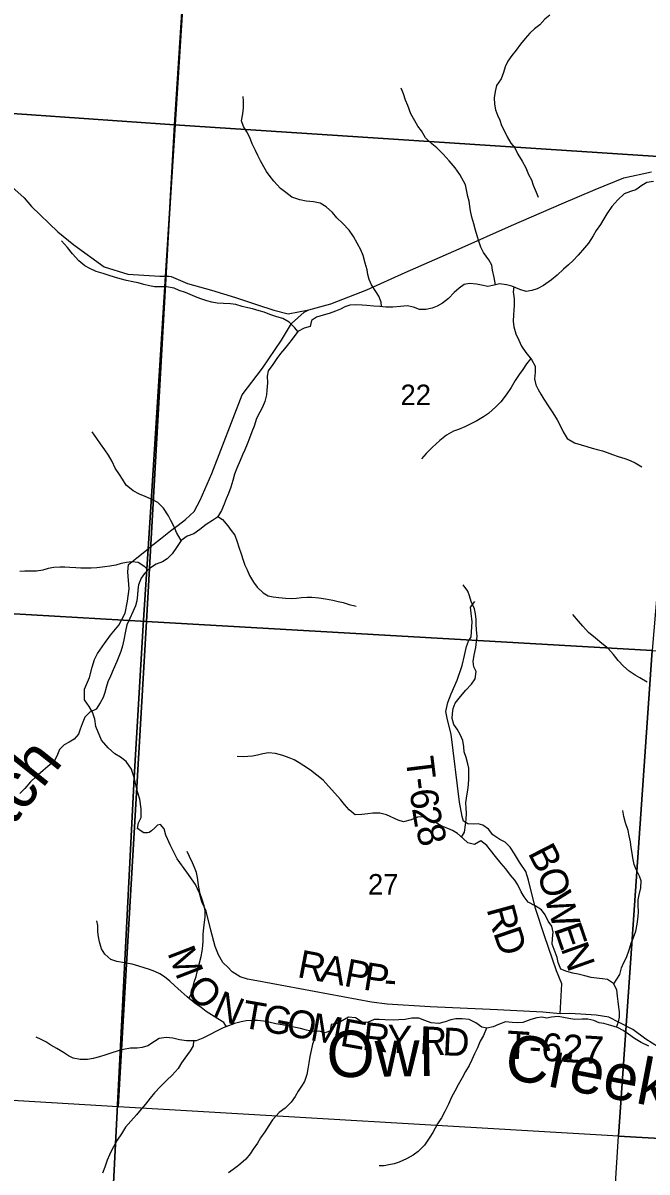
# Model space of a CAD drawing. Extents: x 1578669 to 1989827, y 208020 to 553079.
# Drawn here: x 1838245 to 1844968, y 352759 to 365146 of the extents above; entities that cross this region are included whole.
import ezdxf

# ---------------------------------------------------------------- set-up
doc = ezdxf.new("R2010")
doc.units = 0
for name, color, linetype in [('GM_X_County_Road', 7, 'Continuous'), ('GM_X_Minor_River', 7, 'Continuous'), ('GM_X_Minor_River_Text', 7, 'Continuous'), ('GM_X_Section', 7, 'Continuous'), ('GM_X_Section_Text', 7, 'Continuous'), ('GM_X_Township', 7, 'Continuous'), ('GM_X_Township_Road', 7, 'Continuous'), ('GM_X_Township_Road_Text', 7, 'Continuous')]:
    doc.layers.add(name, color=color, linetype=linetype)

msp = doc.modelspace()

# ---------------------------------------------------------------- linework, layer by layer
at = {"layer": 'GM_X_County_Road'}
for points in [[(1836042, 365335), (1836459, 365085), (1836745, 364850), (1836898, 364717), (1837003, 364579), (1837136, 364380), (1837234, 364169), (1837353, 363879), (1837487, 363752), (1837696, 363686), (1837824, 363590), (1838061, 363436), (1838256, 363262), (1838336, 363168), (1838621, 362894), (1838792, 362754), (1839121, 362517), (1839376, 362437), (1839718, 362416), (1839780, 362416), (1839788, 362417)], [(1839788, 362417), (1839790, 362417), (1839816, 362418), (1839842, 362413), (1840018, 362339), (1840276, 362265), (1840534, 362187), (1840759, 362110), (1840947, 362051), (1841103, 362011), (1841324, 362054), (1841561, 362118), (1841951, 362269), (1842363, 362458), (1842944, 362711), (1843509, 362963), (1844048, 363197), (1844408, 363351), (1844720, 363476), (1845017, 363542)]]:
    msp.add_lwpolyline(points, dxfattribs=at)
at = {"layer": 'GM_X_Minor_River'}
for points in [[(1843921, 365230), (1843868, 365187), (1843814, 365128), (1843755, 365082), (1843704, 365035), (1843656, 364980), (1843605, 364918), (1843557, 364853), (1843511, 364794), (1843468, 364733), (1843440, 364673), (1843423, 364614), (1843397, 364544), (1843348, 364472)], [(1843336, 362324), (1843320, 362404), (1843305, 362481), (1843296, 362535), (1843265, 362594), (1843205, 362671), (1843176, 362730), (1843157, 362794), (1843138, 362853), (1843119, 362913), (1843101, 362982), (1843082, 363052), (1843067, 363122), (1843060, 363173), (1843051, 363227), (1843038, 363277), (1843027, 363328), (1843011, 363402), (1842953, 363512), (1842902, 363585), (1842838, 363660), (1842773, 363731), (1842702, 363801), (1842651, 363844), (1842582, 363908), (1842537, 363983), (1842500, 364035), (1842465, 364090), (1842423, 364167), (1842391, 364256), (1842366, 364315), (1842343, 364381), (1842320, 364444)], [(1843348, 364472), (1843334, 364408), (1843323, 364340), (1843326, 364270), (1843337, 364209), (1843357, 364151), (1843382, 364098), (1843401, 364042), (1843428, 363987), (1843463, 363918), (1843500, 363850), (1843545, 363799), (1843576, 363732), (1843624, 363655), (1843661, 363584), (1843693, 363511), (1843722, 363454), (1843743, 363398), (1843774, 363323), (1843795, 363269)], [(1842107, 362090), (1842105, 362135), (1842077, 362200), (1842048, 362253), (1842001, 362324), (1841976, 362380), (1841961, 362433), (1841952, 362485), (1841933, 362557), (1841911, 362638), (1841886, 362699), (1841844, 362774), (1841805, 362845), (1841758, 362912), (1841688, 362989), (1841625, 363047), (1841578, 363104), (1841513, 363163), (1841445, 363204), (1841374, 363218), (1841296, 363227), (1841226, 363241), (1841142, 363268), (1841075, 363318), (1841018, 363361), (1840948, 363441), (1840909, 363493), (1840869, 363544), (1840838, 363597), (1840804, 363660), (1840775, 363717), (1840750, 363773), (1840713, 363844), (1840688, 363911), (1840658, 363971), (1840619, 364032), (1840598, 364093), (1840613, 364167), (1840622, 364231), (1840622, 364303), (1840617, 364353)], [(1845039, 363439), (1844967, 363426), (1844914, 363395), (1844849, 363346), (1844791, 363329), (1844722, 363303), (1844653, 363238), (1844590, 363167), (1844534, 363088), (1844503, 363036), (1844468, 362975), (1844420, 362908), (1844387, 362850), (1844338, 362773), (1844293, 362722), (1844225, 362643), (1844172, 362584), (1844121, 362539), (1844068, 362492), (1844001, 362429), (1843940, 362376), (1843853, 362316), (1843784, 362281), (1843727, 362264), (1843665, 362251), (1843599, 362272), (1843512, 362310), (1843456, 362325), (1843380, 362335), (1843320, 362320), (1843254, 362307), (1843184, 362319), (1843130, 362330), (1843056, 362339), (1842998, 362326), (1842945, 362289), (1842890, 362240), (1842829, 362175), (1842764, 362124), (1842707, 362095), (1842655, 362072), (1842584, 362058), (1842518, 362059), (1842453, 362082), (1842385, 362096), (1842311, 362091), (1842229, 362081), (1842155, 362084), (1842091, 362091), (1842025, 362095), (1841951, 362100)], [(1841207, 361822), (1841175, 361859), (1841112, 361920), (1841043, 361960), (1840979, 361977), (1840906, 362004), (1840844, 362028), (1840788, 362043), (1840719, 362064), (1840667, 362077), (1840607, 362090), (1840538, 362110), (1840480, 362119), (1840404, 362123), (1840338, 362126), (1840278, 362135), (1840226, 362152), (1840172, 362169), (1840121, 362188), (1840047, 362218), (1839996, 362239), (1839928, 362264), (1839874, 362287), (1839791, 362301), (1839722, 362300), (1839662, 362301), (1839607, 362311), (1839545, 362326), (1839485, 362345), (1839429, 362354), (1839359, 362370), (1839290, 362387), (1839232, 362406), (1839174, 362423), (1839107, 362445), (1839033, 362468), (1838964, 362500), (1838912, 362529), (1838847, 362582), (1838778, 362656), (1838726, 362725), (1838659, 362796)], [(1843532, 362301), (1843525, 362248), (1843538, 362173), (1843538, 362103), (1843533, 362049), (1843530, 361999), (1843527, 361933), (1843532, 361869), (1843554, 361796), (1843587, 361727), (1843616, 361661), (1843662, 361594), (1843725, 361518), (1843762, 361446), (1843764, 361381), (1843757, 361309), (1843770, 361245), (1843797, 361194), (1843826, 361144), (1843855, 361091), (1843902, 361018), (1843954, 360943), (1844001, 360868), (1844037, 360799), (1844066, 360738), (1844107, 360665), (1844186, 360620), (1844260, 360598), (1844320, 360581), (1844377, 360564), (1844433, 360549), (1844489, 360533), (1844540, 360516), (1844598, 360493), (1844658, 360474), (1844729, 360451), (1844785, 360431), (1844839, 360406), (1844912, 360361)], [(1841951, 362100), (1841899, 362105), (1841829, 362109), (1841765, 362104), (1841714, 362087), (1841664, 362062), (1841611, 362041), (1841543, 362016), (1841480, 361997), (1841408, 361975), (1841353, 361940), (1841340, 361874), (1841273, 361857), (1841207, 361822), (1841145, 361739), (1841104, 361688), (1841061, 361635), (1841020, 361583), (1840981, 361530), (1840935, 361463), (1840888, 361398), (1840877, 361340), (1840878, 361267), (1840872, 361189), (1840869, 361139), (1840852, 361064), (1840826, 361004), (1840795, 360952), (1840762, 360883), (1840734, 360799), (1840711, 360738), (1840686, 360670), (1840659, 360604), (1840635, 360545), (1840610, 360491), (1840585, 360430), (1840550, 360348), (1840524, 360284), (1840507, 360213), (1840484, 360143), (1840458, 360073), (1840435, 360016), (1840414, 359960), (1840385, 359890), (1840339, 359817), (1840286, 359782), (1840220, 359741), (1840150, 359685), (1840085, 359640), (1840015, 359615), (1839948, 359566), (1839900, 359491), (1839853, 359424), (1839798, 359371), (1839747, 359338), (1839679, 359311), (1839608, 359264), (1839555, 359211), (1839518, 359160), (1839490, 359088), (1839481, 359036), (1839480, 358982), (1839471, 358918), (1839456, 358862), (1839429, 358799), (1839395, 358725), (1839364, 358658), (1839349, 358590), (1839331, 358498), (1839317, 358430), (1839298, 358369), (1839277, 358317), (1839254, 358261), (1839218, 358174), (1839187, 358106), (1839160, 358043), (1839141, 357981), (1839126, 357929), (1839107, 357873), (1839077, 357816), (1839032, 357749), (1838965, 357716), (1838910, 357663), (1838883, 357591), (1838860, 357533), (1838841, 357478), (1838796, 357426), (1838741, 357394), (1838688, 357366), (1838639, 357313), (1838610, 357242), (1838581, 357188), (1838514, 357129), (1838463, 357088), (1838383, 357018), (1838324, 356965), (1838265, 356892), (1838212, 356841)], [(1843716, 361530), (1843670, 361471), (1843631, 361412), (1843590, 361355), (1843547, 361291), (1843503, 361216), (1843451, 361137), (1843392, 361062), (1843343, 361011), (1843261, 360936), (1843207, 360899), (1843134, 360857), (1843055, 360816), (1843004, 360793), (1842938, 360764), (1842885, 360747), (1842807, 360703), (1842737, 360644), (1842656, 360575), (1842590, 360504), (1842537, 360449)], [(1839950, 359568), (1839900, 359655), (1839877, 359706), (1839838, 359783), (1839811, 359833), (1839758, 359915), (1839696, 359976), (1839618, 360016), (1839561, 360043), (1839501, 360068), (1839432, 360101), (1839357, 360163), (1839316, 360228), (1839285, 360279), (1839238, 360348), (1839206, 360417), (1839165, 360488), (1839128, 360546), (1839079, 360611), (1839042, 360666), (1838990, 360737)], [(1840344, 359825), (1840393, 359792), (1840452, 359727), (1840489, 359676), (1840528, 359623), (1840554, 359552), (1840571, 359494), (1840594, 359425), (1840617, 359355), (1840636, 359302), (1840661, 359250), (1840685, 359189), (1840730, 359118), (1840769, 359065), (1840834, 359002), (1840887, 358969), (1840939, 358960), (1841003, 358954), (1841073, 358945), (1841137, 358942), (1841193, 358945), (1841247, 358954), (1841306, 358958), (1841358, 358957), (1841433, 358950), (1841505, 358940), (1841583, 358923), (1841639, 358910), (1841693, 358897), (1841760, 358877), (1841836, 358858)], [(1839591, 359248), (1839558, 359283), (1839485, 359329), (1839419, 359336), (1839361, 359331), (1839301, 359318), (1839244, 359302), (1839180, 359289), (1839128, 359282), (1839039, 359271), (1838981, 359269), (1838931, 359270), (1838867, 359269), (1838815, 359272), (1838749, 359275), (1838697, 359278), (1838643, 359279), (1838577, 359275), (1838515, 359264), (1838460, 359249), (1838390, 359238), (1838336, 359237), (1838264, 359237), (1838212, 359232)], [(1842971, 356368), (1843002, 356422), (1843014, 356502), (1843021, 356560), (1843024, 356628), (1843019, 356682), (1843016, 356740), (1843026, 356814), (1843039, 356876), (1843046, 356936), (1843049, 356996), (1843050, 357054), (1843047, 357111), (1843038, 357161), (1843018, 357229), (1842999, 357290), (1842994, 357342), (1842983, 357410), (1842956, 357475), (1842924, 357534), (1842888, 357585), (1842868, 357649), (1842871, 357703), (1842878, 357755), (1842903, 357815), (1842960, 357886), (1843016, 357953), (1843077, 358018), (1843116, 358075), (1843126, 358155), (1843103, 358206), (1843096, 358262), (1843107, 358332), (1843123, 358414), (1843132, 358478), (1843137, 358534), (1843132, 358606), (1843127, 358662), (1843127, 358716), (1843122, 358775), (1843109, 358831), (1843072, 358908), (1843057, 358970), (1843036, 359021), (1842986, 359088)], [(1844969, 358039), (1844892, 358087), (1844840, 358114), (1844777, 358157), (1844714, 358212), (1844659, 358272), (1844607, 358339), (1844550, 358402), (1844483, 358457), (1844412, 358515), (1844339, 358576), (1844278, 358642), (1844231, 358699), (1844170, 358770)], [(1844641, 354320), (1844660, 354378), (1844671, 354429), (1844672, 354486), (1844665, 354538), (1844659, 354598), (1844652, 354656), (1844643, 354723), (1844608, 354793), (1844543, 354835), (1844487, 354842), (1844423, 354849), (1844367, 354856), (1844300, 354874), (1844226, 354891), (1844170, 354904), (1844106, 354921), (1844041, 354947), (1844010, 355018), (1843999, 355072), (1843946, 355217), (1843949, 355275), (1843958, 355345), (1843942, 355410), (1843905, 355463), (1843872, 355533), (1843831, 355584), (1843762, 355628), (1843688, 355669), (1843643, 355724), (1843612, 355779), (1843578, 355854), (1843545, 355906), (1843496, 355960), (1843447, 356027), (1843396, 356086), (1843337, 356159), (1843283, 356228), (1843242, 356279), (1843177, 356328), (1843108, 356290), (1843038, 356309), (1842987, 356354), (1842926, 356408), (1842872, 356441), (1842821, 356462), (1842749, 356491), (1842698, 356524), (1842644, 356553), (1842575, 356589), (1842495, 356584), (1842428, 356554), (1842346, 356535), (1842288, 356552), (1842163, 356609), (1842089, 356628), (1842013, 356626), (1841959, 356621), (1841895, 356614), (1841825, 356611), (1841760, 356663), (1841709, 356720), (1841664, 356775), (1841605, 356844), (1841538, 356918), (1841478, 356985), (1841411, 357038), (1841342, 357090), (1841272, 357139), (1841219, 357172), (1841168, 357202), (1841112, 357223), (1841044, 357248), (1840967, 357272), (1840889, 357277), (1840828, 357266), (1840772, 357253), (1840718, 357242), (1840668, 357237), (1840618, 357236), (1840554, 357240)], [(1844611, 354788), (1844674, 354890), (1844694, 354960), (1844719, 355016), (1844748, 355071), (1844775, 355153), (1844799, 355225), (1844824, 355288), (1844847, 355354), (1844863, 355430), (1844872, 355512), (1844875, 355564), (1844873, 355632), (1844874, 355694), (1844883, 355746), (1844902, 355824), (1844906, 355898), (1844889, 355948), (1844852, 356019), (1844831, 356076), (1844817, 356146), (1844808, 356198), (1844797, 356257), (1844790, 356319), (1844777, 356385), (1844764, 356440), (1844738, 356524), (1844719, 356593), (1844706, 356657)], [(1840034, 354633), (1840064, 354696), (1840075, 354748), (1840090, 354804), (1840110, 354866), (1840123, 354917), (1840166, 355081), (1840177, 355141), (1840182, 355199), (1840185, 355253), (1840186, 355323), (1840192, 355391), (1840199, 355453), (1840208, 355505), (1840209, 355573), (1840198, 355629), (1840176, 355698), (1840153, 355758), (1840140, 355829), (1840133, 355879), (1840124, 355933), (1840113, 355988), (1840094, 356042), (1840071, 356093), (1840040, 356160), (1840015, 356216)], [(1840438, 354326), (1840410, 354371), (1840345, 354412), (1840274, 354455), (1840218, 354489), (1840163, 354532), (1840096, 354581), (1840015, 354649), (1839948, 354704), (1839877, 354770), (1839826, 354817), (1839769, 354862), (1839718, 354897), (1839666, 354922), (1839609, 354944), (1839549, 354961), (1839493, 354980), (1839421, 355001), (1839338, 355013), (1839254, 355027), (1839192, 355050), (1839125, 355107), (1839092, 355166), (1839070, 355239), (1839059, 355295), (1839052, 355347), (1839051, 355415), (1839042, 355466)], [(1844988, 354115), (1844904, 354156), (1844835, 354200), (1844770, 354245), (1844713, 354284), (1844649, 354318), (1844579, 354339), (1844504, 354361), (1844452, 354368), (1844394, 354391), (1844329, 354408), (1844271, 354407), (1844192, 354403), (1844125, 354414), (1844069, 354425), (1844011, 354436), (1843939, 354430), (1843888, 354417), (1843835, 354428), (1843782, 354421), (1843716, 354404), (1843629, 354372), (1843575, 354367), (1843515, 354372), (1843443, 354379), (1843367, 354351), (1843310, 354326), (1843242, 354309), (1843190, 354320), (1843125, 354368), (1843053, 354403), (1842977, 354411), (1842909, 354410), (1842853, 354399), (1842795, 354378), (1842724, 354359), (1842644, 354367), (1842575, 354394), (1842511, 354416), (1842433, 354417), (1842363, 354405), (1842295, 354400), (1842236, 354395), (1842148, 354399), (1842084, 354404), (1842028, 354403), (1841958, 354372), (1841898, 354374), (1841827, 354421), (1841753, 354430), (1841684, 354390), (1841627, 354359), (1841565, 354348), (1841556, 354280), (1841501, 354261), (1841437, 354278), (1841365, 354274), (1841299, 354287), (1841234, 354306), (1841162, 354322), (1841092, 354335), (1841036, 354344), (1840969, 354358), (1840893, 354375), (1840837, 354386), (1840773, 354392), (1840721, 354393), (1840651, 354388), (1840595, 354379), (1840522, 354360), (1840460, 354334), (1840403, 354313), (1840328, 354278), (1840256, 354239), (1840183, 354203), (1840112, 354172), (1840062, 354173), (1840006, 354172), (1839930, 354184), (1839858, 354201)], [(1841387, 354275), (1841388, 354203), (1841365, 354138), (1841351, 354068), (1841336, 354004), (1841325, 353936), (1841313, 353870), (1841302, 353812), (1841279, 353736), (1841246, 353685), (1841209, 353630), (1841178, 353574), (1841134, 353511), (1841071, 353448), (1841004, 353399), (1840932, 353320), (1840895, 353259), (1840852, 353192), (1840805, 353126), (1840772, 353071), (1840724, 353006), (1840691, 352954), (1840644, 352899), (1840567, 352831), (1840510, 352788), (1840459, 352750)], [(1843238, 354310), (1843206, 354232), (1843171, 354170), (1843142, 354099), (1843110, 354033), (1843081, 353970), (1843052, 353908), (1843012, 353841), (1842977, 353773), (1842932, 353700), (1842896, 353629), (1842863, 353565), (1842829, 353490), (1842790, 353412), (1842753, 353345), (1842711, 353277), (1842661, 353186), (1842630, 353133), (1842571, 353050), (1842501, 352981), (1842447, 352942), (1842376, 352901), (1842299, 352867), (1842243, 352846), (1842188, 352835), (1842136, 352826), (1842082, 352827)], [(1839858, 354201), (1839787, 354209), (1839712, 354198), (1839660, 354167), (1839591, 354120), (1839530, 354101), (1839476, 354096), (1839402, 354094), (1839326, 354081), (1839269, 354066), (1839191, 354040), (1839138, 354021), (1839068, 354000), (1839001, 353984), (1838939, 353971), (1838861, 353972), (1838787, 353988), (1838736, 354013), (1838680, 354046), (1838609, 354089), (1838544, 354127), (1838492, 354164), (1838441, 354189), (1838387, 354214)], [(1840082, 354173), (1840077, 354119), (1840046, 354067), (1839990, 353988), (1839953, 353935), (1839918, 353875), (1839853, 353804), (1839796, 353751), (1839726, 353681), (1839663, 353612), (1839616, 353555), (1839565, 353491), (1839517, 353436), (1839466, 353377), (1839407, 353308), (1839350, 353243), (1839306, 353170), (1839261, 353101), (1839203, 352998), (1839178, 352946), (1839152, 352888), (1839127, 352813), (1839102, 352745)]]:
    msp.add_lwpolyline(points, dxfattribs=at)
at = {"layer": 'GM_X_Section'}
for points in [[(1840233, 369517), (1839878, 364047), (1834739, 364406), (1835019, 369840)], [(1845843, 369059), (1845472, 363681), (1839878, 364047), (1840233, 369517)], [(1839878, 364047), (1839574, 358693), (1834369, 358996), (1834739, 364406)], [(1845472, 363681), (1845025, 358383), (1839574, 358693), (1839878, 364047)], [(1834369, 358996), (1839574, 358693), (1839269, 353462), (1833998, 353777)], [(1839574, 358693), (1845025, 358383), (1844662, 353144), (1839269, 353462)], [(1845025, 358383), (1850307, 358069), (1849954, 352849), (1844662, 353144)], [(1849954, 352849), (1849557, 347455), (1844321, 347760), (1844662, 353144)]]:
    msp.add_lwpolyline(points, close=True, dxfattribs=at)
at = {"layer": 'GM_X_Township'}
for points in [[(1840250, 369801), (1839780, 362417), (1839593, 359479), (1839540, 358655), (1839441, 357011), (1839041, 349111), (1838968, 348044), (1835528, 348231), (1834882, 348273), (1833762, 348331), (1833481, 348350), (1833224, 348359), (1831370, 348458), (1826336, 348649), (1819510, 348957), (1818598, 348960), (1813935, 349079)], [(1860651, 356303), (1860040, 346806), (1858312, 346913), (1856863, 346996), (1854820, 347140), (1849999, 347391), (1848416, 347480), (1846968, 347563), (1845155, 347665), (1844797, 347685), (1838968, 348044), (1839041, 349111), (1839441, 357011), (1839540, 358655), (1839593, 359479), (1839780, 362417), (1840250, 369801)]]:
    msp.add_lwpolyline(points, dxfattribs=at)
at = {"layer": 'GM_X_Township_Road'}
for points in [[(1839632, 359511), (1839643, 359520), (1839728, 359586), (1839835, 359672), (1839915, 359733), (1839994, 359795), (1840090, 359879), (1840153, 360001), (1840279, 360289), (1840606, 361136), (1840824, 361426), (1841030, 361726), (1841139, 361908), (1841275, 362029), (1841324, 362054)], [(1839422, 357076), (1839422, 357076), (1839414, 357101), (1839355, 357184), (1839295, 357230), (1839233, 357269), (1839161, 357332), (1839089, 357414), (1839030, 357563), (1839020, 357641), (1838993, 357716), (1838957, 357776), (1838909, 357851), (1838908, 357965), (1838960, 358089), (1838991, 358203), (1839016, 358284), (1839048, 358348), (1839123, 358458), (1839189, 358547), (1839276, 358655), (1839345, 358785), (1839372, 358912), (1839390, 359046), (1839373, 359231), (1839382, 359307), (1839472, 359381), (1839593, 359479), (1839631, 359511), (1839632, 359511)], [(1844032, 354466), (1844051, 354789), (1843992, 354929), (1843862, 355307), (1843765, 355599), (1843692, 355904), (1843661, 355999), (1843595, 356101), (1843539, 356188), (1843494, 356261), (1843440, 356315), (1843382, 356345), (1843308, 356394), (1843262, 356454), (1843200, 356497), (1843150, 356513), (1843102, 356509), (1843036, 356514), (1842990, 356540), (1842978, 356590), (1842949, 356747), (1842858, 357478), (1842817, 357633), (1842801, 357725), (1842824, 357821), (1842859, 357915), (1842923, 358060), (1842976, 358218), (1843001, 358328), (1843022, 358424), (1843044, 358482), (1843072, 358528), (1843083, 358689), (1843073, 358785), (1843068, 358847), (1843114, 358911)], [(1840491, 354926), (1840456, 354963), (1840398, 355017), (1840352, 355102), (1840317, 355192), (1840270, 355367), (1840217, 355570), (1840173, 355672), (1840145, 355767), (1840102, 355857), (1840010, 355990), (1839907, 356135), (1839835, 356278), (1839782, 356389), (1839766, 356459), (1839728, 356504), (1839694, 356500), (1839664, 356468), (1839630, 356438), (1839605, 356420), (1839587, 356414), (1839547, 356416), (1839517, 356435), (1839477, 356463), (1839490, 356525), (1839498, 356539), (1839518, 356581), (1839519, 356673), (1839503, 356778), (1839479, 356858), (1839441, 357011), (1839422, 357076)], [(1845092, 354105), (1844956, 354192), (1844817, 354297), (1844669, 354370), (1844557, 354429), (1844422, 354451), (1844256, 354462), (1844134, 354467), (1844032, 354466), (1843845, 354483), (1843358, 354509), (1842631, 354541), (1842168, 354570), (1841998, 354589), (1840764, 354820), (1840662, 354839), (1840586, 354862), (1840498, 354918), (1840491, 354926), (1840491, 354926)]]:
    msp.add_lwpolyline(points, dxfattribs=at)

# ---------------------------------------------------------------- texts
at = {"layer": 'GM_X_Minor_River_Text'}
for s, rotation, p in [('Dutch', 51.3848, (1837595, 355811)), ('Owl', 0.8423, (1841519, 353779)), ('Creek', 349.2063, (1843409, 353776))]:
    msp.add_text(s, height=500, rotation=rotation, dxfattribs=at).set_placement(p)
at = {"layer": 'GM_X_Section_Text'}
for s, p in [('22', (1842312, 361027)), ('27', (1841962, 355750))]:
    msp.add_text(s, height=221, rotation=0, dxfattribs=at).set_placement(p)
at = {"layer": 'GM_X_Township_Road_Text'}
for s, rotation, p in [('T', 277.0118, (1842367, 357221)), ('6', 277.303, (1842410, 356875)), ('-', 277.0817, (1842395, 356998)), ('2', 279.3358, (1842435, 356680)), ('8', 285.4616, (1842473, 356463)), ('B', 297.176, (1843679, 356199)), ('O', 284.6618, (1843786, 355996)), ('W', 287.1217, (1843856, 355727)), ('R', 285.2935, (1843238, 355595)), ('D', 288.6515, (1843309, 355340)), ('E', 288.9245, (1843962, 355385)), ('M', 291.1877, (1839797, 355123)), ('R', 349.2152, (1841190, 354862)), ('N', 289.5978, (1844036, 355170)), ('A', 349.2208, (1841432, 354816)), ('P', 349.3028, (1841692, 354767)), ('P', 351.0905, (1841901, 354727)), ('O', 313.6426, (1839983, 354711)), ('-', 356.086, (1842129, 354693)), ('N', 336.6887, (1840273, 354446)), ('T', 350.1214, (1840589, 354319)), ('G', 349.3195, (1840809, 354281)), ('O', 349.3843, (1841069, 354232)), ('M', 349.424, (1841328, 354183)), ('E', 349.7794, (1841650, 354123)), ('R', 353.3677, (1841891, 354080)), ('Y', 356.9901, (1842157, 354050)), ('R', 357.1674, (1842514, 354032)), ('D', 357.189, (1842760, 354019)), ('T-627', 356.3939, (1843446, 353985))]:
    msp.add_text(s, height=300, rotation=rotation, dxfattribs=at).set_placement(p)

doc.saveas('drawing.dxf')
